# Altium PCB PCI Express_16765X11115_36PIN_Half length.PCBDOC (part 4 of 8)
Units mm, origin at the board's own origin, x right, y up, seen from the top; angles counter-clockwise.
Board outline 178 x 110.97 mm, 10 copper layers (Top Layer, Int1 (GND), Int2 (Sign), Int3 (Sign), Int4 (PWR), Int5 (GND), Int6 (Sign), Int7 (Sign), Int8 (GND), Bottom Layer), stack 1.429 mm thick; 528 components, 525 nets, 2272 pads, 1491 vias.
Unrouted connection lines stored in the file: 373.
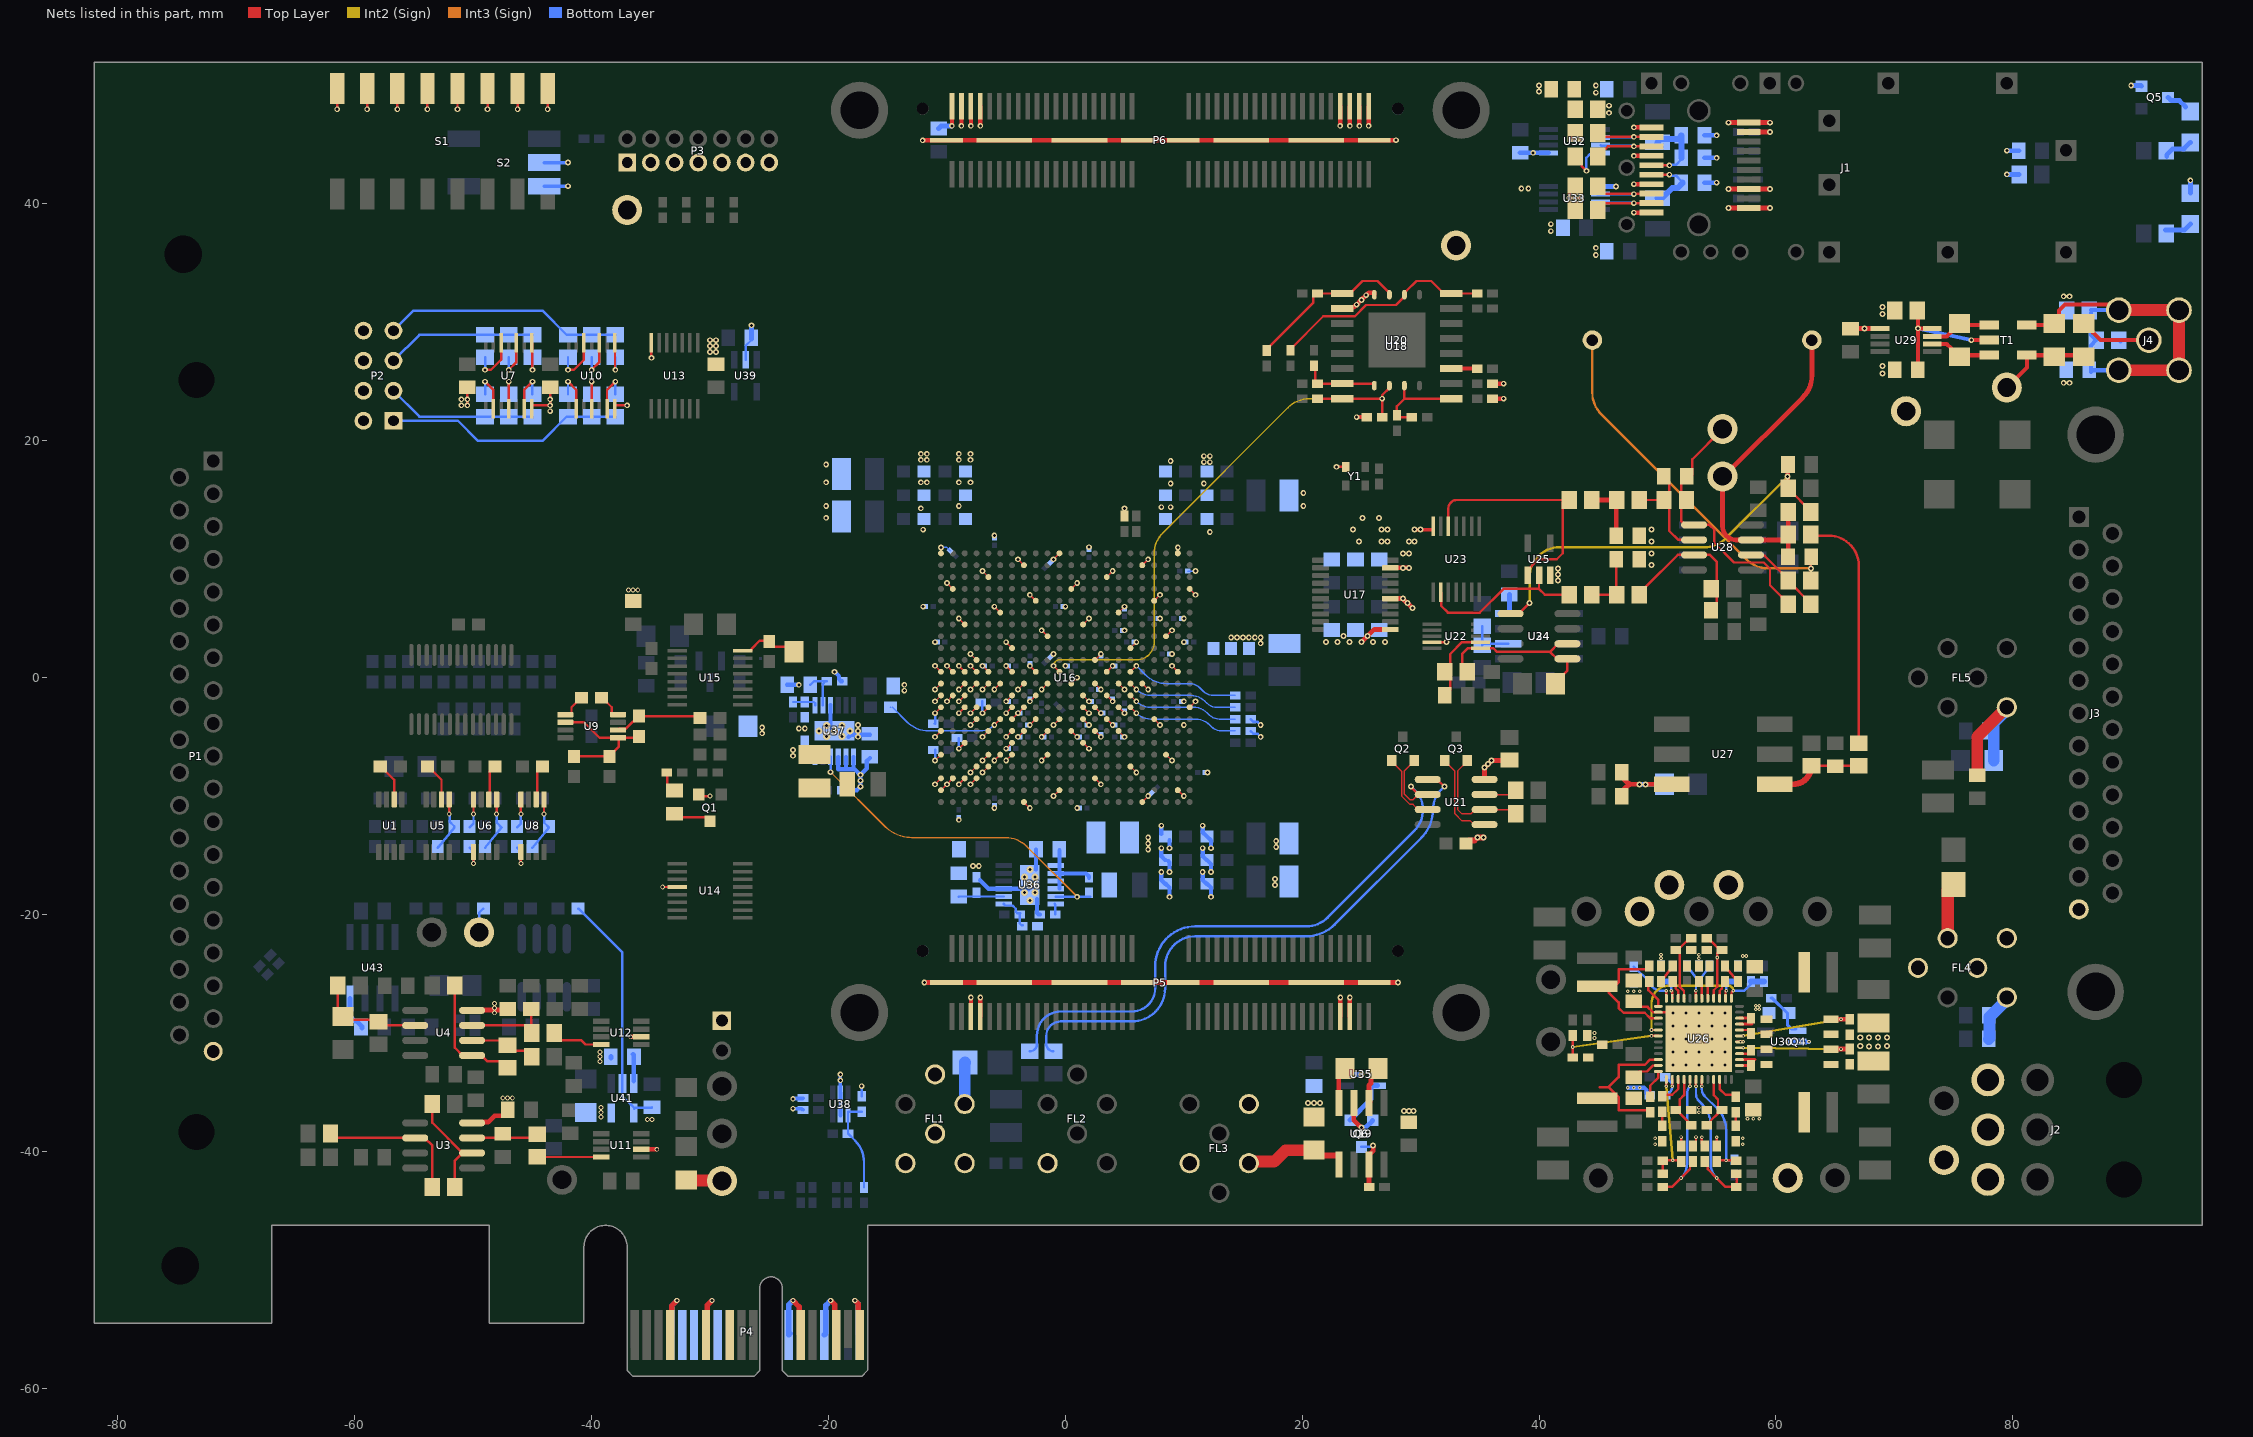
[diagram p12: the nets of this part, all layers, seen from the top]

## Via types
v1: diameter 0.483, hole 0.254, Top Layer to Bottom Layer, tented both sides, 740 vias
v2: diameter 0.508, hole 0.254, Top Layer to Bottom Layer, tented both sides, 302 vias
v3: diameter 0.406, hole 0.254, Top Layer to Bottom Layer, tented both sides, 267 vias
v4: diameter 0.305, hole 0.152, Top Layer to Bottom Layer, tented both sides, 95 vias
v5: diameter 0.5, hole 0.254, Top Layer to Bottom Layer, tented both sides, 50 vias
v6: diameter 0.45, hole 0.254, Top Layer to Bottom Layer, tented both sides, 23 vias
v7: diameter 0.6, hole 0.254, Top Layer to Bottom Layer, tented both sides, 14 vias

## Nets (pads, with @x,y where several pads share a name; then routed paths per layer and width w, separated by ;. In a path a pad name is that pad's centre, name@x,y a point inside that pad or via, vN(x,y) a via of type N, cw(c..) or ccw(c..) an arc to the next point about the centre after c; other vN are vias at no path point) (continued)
GND: C6.2 C12.2 C18.2 C23.2 C25.1 C26.1 C28.2 C29.2 C31.1 C32.1 C35.1 C37.1 C40.1 C41.2 C42.1 C43.2 C44.2 C45.1 C46.1 C50.1 C51.1 C52.2 C53.1 C56.1 C57.1 C58.2 C59.2 C67.2 C68.2 C69.1 C70.1 C73.2 C74.1 C75.2 C76.1 C77.2 C78.2 C79.2 C80.2 C83.1 C84.1 C85.1 C86.1 C87.1 C89.1 C91.1 C93.1 C94.1 C95.1 C96.1 C97.1 C98.1 C99.1 C100.1 C101.1 C102.1 C103.1 C104.1 C105.1 C106.1 C107.1 C108.1 C109.1 C110.1 C111.1 C112.1 C113.1 C114.1 C115.1 C116.1 C117.1 C118.1 C119.1 C120.1 C121.1 C122.1 C123.1 C124.1 C125.1 C126.1 C127.1 C128.1 C129.2 C130.1 C131.2 C132.1 C133.2 C134.1 C135.1 C136.2 C137.2 C138.1 C139.2 C140.1 C141.1 C142.1 C143.2 C144.2 C145.1 C147.1 C148.1 C149.1 C150.1 C151.2 C153.1 C154.1 C155.2 C156.2 C157.2 C158.1 C159.1 C160.2 C161.1 C162.1 C163.1 C164.1 C165.1 C166.1 C167.1 C168.1 C169.1 C170.1 C171.1 C172.1 C173.1 C174.1 C175.1 C176.1 C177.1 C178.1 C179.1 C180.1 C181.1 C182.1 C183.1 C184.1 C187.2 C188.2 C189.1 C192.1 DS2.1 FL1.3 FL1.4 FL1.5 FL1.6 FL2.3 FL3.3 FL4.3 FL4.4 FL4.5 FL4.6 FL5.3 FR4.1 J1.1 J1.3 J1.9 J1.10 J1.11 J1.14 J1.17 J1.20 J2.4 J2.5 J2.6 J3.13 P1.19 P2.2 P2.4 P2.6 P2.8 P3.1 P3.3 P3.5 P3.7 P3.9 P3.11 P3.13 P4.A4 P4.A12 P4.A15 P4.A18 P4.B4 P4.B7 P4.B13 P4.B16 P4.B18 P5.5 P5.7 P5.73 P5.75 P5.81 P5.82 P5.83 P5.84 P5.85 P5.86 P5.87 P5.88 P6.2 P6.4 P6.6 P6.8 P6.74 P6.76 P6.78 P6.80 P6.81 P6.82 P6.83 P6.84 P6.85 P6.86 P6.87 P6.88 Q1.2 Q4.1 Q4.3 Q5.2 Q6.2 R28.2 R36.2 R45.1 R52.2 R53.2 R54.1 R57.2 R69.2 R70.2 R71.2 R73.1 R74.2 R75.2 R76.2 R80.2 R81.2 R93.2 R94.2 R98.2 R106.2 R107.2 R114.1 R115.1 R119.2 R122.1 R124.1 R126.1 R131.2 R132.2 R137.1 R138.1 R143.1 R146.1 R149.1 R150.1 R151.1 S1.1 S1.2 S1.3 S1.4 S1.5 S1.6 S1.7 S1.8 S2.3 S2.5 TP4.1 TP8.1 TP13.1 TP14.1 TP18.1 TP20.1 TP23.1 TP24.1 U7.7 U10.7 U11.6 U12.6 U13.7 U14.12 U16.A2 U16.A3 U16.A5 U16.A7 U16.A9 U16.A10 U16.A11 U16.A12 U16.A22 U16.AA2 U16.AA12 U16.AA22 U16.AB9 U16.AB19 U16.B3 U16.B10 U16.B12 U16.B19 U16.C3 U16.C6 U16.C9 U16.C10 U16.C11 U16.C12 U16.C16 U16.D3 U16.D4 U16.D8 U16.D9 U16.D11 U16.D12 U16.D13 U16.E4 U16.E5 U16.E7 U16.E9 U16.E11 U16.E12 U16.E20 U16.F5 U16.F11 U16.F17 U16.G5 U16.G6 U16.G7 U16.G8 U16.G9 U16.G10 U16.G12 U16.G14 U16.H1 U16.H7 U16.H9 U16.H11 U16.H21 U16.J8 U16.J10 U16.J12 U16.J18 U16.K5 U16.K7 U16.K11 U16.K15 U16.L2 U16.L8 U16.L22 U16.M7 U16.M11 U16.M19 U16.N6 U16.N8 U16.N9 U16.N10 U16.N16 U16.P3 U16.P7 U16.P9 U16.P11 U16.P13 U16.R8 U16.R10 U16.R12 U16.R20 U16.T7 U16.T9 U16.T11 U16.T17 U16.U4 U16.U14 U16.V1 U16.V11 U16.V21 U16.W8 U16.W18 U16.Y5 U16.Y15 U17.11 U17.15 U17.19 U18.10 U19.3 U20.4 U21.4 U22.9 U23.7 U25.3 U26.2 U26.11 U26.30 U26.49 U29.5 U30.2 U32.5 U33.5 U35.2 U36.9 U36.13 U37.9 U37.13 U38.2 U38.5 U39.2 W1.1 Y1.2 | length 367.5
  Top Layer w0.127: v1(-11,-9) U16.A3@-10.5,-8.5 ; v1(-11,-7) U16.A5@-10.5,-6.5 ; v1(-11,-5) U16.A7@-10.5,-4.5 ; v1(-11,-3) U16.A9@-10.5,-2.5 ; v1(-11,-2) U16.A10@-10.5,-1.5 ; v1(-11,-1) U16.A11@-10.5,-0.5 ; v1(-11,1) U16.A12@-10.5,0.5 ; U16.A2@-10.5,-9.5 v1(-10,-9) U16.B3@-9.5,-8.5 ; U16.A22@-10.5,10.5 v1(-10.5,11) ; v1(-10,-2) U16.B10@-9.5,-1.5 ; v1(-10,1) U16.B12@-9.5,0.5 ; v1(-10,8) U16.B19@-9.5,7.5 ; v1(-9,-9) U16.C3@-8.5,-8.5 ; v1(-9,-6) U16.C6@-8.5,-5.5 ; v1(-9,-3) U16.C9@-8.5,-2.5 ; v1(-9,-2) U16.C10@-8.5,-1.5 ; v1(-9,-1) U16.C11@-8.5,-0.5 ; v1(-9,1) U16.C12@-8.5,0.5 ; v1(-9,5) U16.C16@-8.5,4.5 ; v1(-8,-9) U16.D3@-7.5,-8.5 ; v1(-8,-8) U16.D4@-7.5,-7.5 ; v1(-8,-4) U16.D8@-7.5,-3.5 ; v1(-8,-3) U16.D9@-7.5,-2.5 ; v1(-8,-1) U16.D11@-7.5,-0.5 ; v1(-8,1) U16.D12@-7.5,0.5 ; v1(-8,2) U16.D13@-7.5,1.5 ; v1(-7,-8) U16.E4@-6.5,-7.5 ; v1(-7,-7) U16.E5@-6.5,-6.5 ; v1(-7,-5) U16.E7@-6.5,-4.5 ; v1(-7,-3) U16.E9@-6.5,-2.5 ; v1(-7,-1) U16.E11@-6.5,-0.5 ; v1(-7,1) U16.E12@-6.5,0.5 ; v1(-7,9) U16.E20@-6.5,8.5 ; v1(-6,-7) U16.F5@-5.5,-6.5 ; v1(-6,-1) U16.F11@-5.5,-0.5 ; v1(-6,6) U16.F17@-5.5,5.5 ; v1(-5,-7) U16.G5@-4.5,-6.5 ; v1(-5,-6) U16.G6@-4.5,-5.5 ; v1(-5,-5) U16.G7@-4.5,-4.5 ; v1(-5,-3) U16.G9@-4.5,-2.5 ; v1(-5,-2) U16.G10@-4.5,-1.5 ; v1(-5,1) U16.G12@-4.5,0.5 ; v1(-5,3) U16.G14@-4.5,2.5 ; U16.G8@-4.5,-3.5 v1(-4,-3) U16.H9@-3.5,-2.5 ; v1(-4,-5) U16.H7@-3.5,-4.5 ; v1(-4,-1) U16.H11@-3.5,-0.5 ; v1(-4,10) U16.H21@-3.5,9.5 ; U16.H1@-3.5,-10.5 -3.514,-10.514 -3.029,-11 v1(-3,-11) ; v1(-3,-4) U16.J8@-2.5,-3.5 ; v1(-3,-2) U16.J10@-2.5,-1.5 ; v1(-3,1) U16.J12@-2.5,0.5 ; v1(-3,7) U16.J18@-2.5,6.5 ; v1(-2,-7) U16.K5@-1.5,-6.5 ; v1(-2,-5) U16.K7@-1.5,-4.5 ; v1(-2,-1) U16.K11@-1.5,-0.5 ; v1(-2,4) U16.K15@-1.5,3.5 ; v1(-1,-10) U16.L2@-0.5,-9.5 ; v1(-1,-4) U16.L8@-0.5,-3.5 ; v1(-1,10) U16.L22@-0.5,10.5 ; U16.M7@0.5,-4.5 v1(1,-5) ; U16.M19@0.5,7.5 v1(1,8) ; U16.N6@1.5,-5.5 v1(2,-6) ; U16.N8@1.5,-3.5 v1(2,-4) ; U16.N9@1.5,-2.5 v1(2,-3) ; U16.N10@1.5,-1.5 v1(2,-2) ; U16.N16@1.5,4.5 v1(2,5) ; U16.P3@2.5,-8.5 v1(3,-9) ; U16.P7@2.5,-4.5 v1(3,-5) ; U16.P9@2.5,-2.5 v1(3,-3) ; U16.P11@2.5,-0.5 v1(3,-1) ; U16.P13@2.5,1.5 v1(3,2) ; U16.R8@3.5,-3.5 v1(4,-4) ; U16.R10@3.5,-1.5 v1(4,-2) ; U16.R12@3.5,0.5 v1(4,1) ; U16.R20@3.5,8.5 v1(4,9) ; U16.T7@4.5,-4.5 v1(5,-5) ; U16.T9@4.5,-2.5 v1(5,-3) ; U16.T11@4.5,-0.5 v1(5,-1) ; U16.T17@4.5,5.5 v1(5,6) ; U16.U4@5.5,-7.5 v1(6,-8) ; U16.U14@5.5,2.5 v1(6,3) ; U16.V1@6.5,-10.5 v1(7,-10) ; U16.V11@6.5,-0.5 v1(7,-1) ; U16.V21@6.5,9.5 v1(7,10) ; U16.W8@7.5,-3.5 v1(8,-4) ; U16.W18@7.5,6.5 v1(8,7) ; U16.Y5@8.5,-6.5 v1(9,-7) ; U16.Y15@8.5,3.5 v1(9,4) ; v1(9,1) U16.AA12@9.5,0.5 ; U16.AA2@9.5,-9.5 v1(10,-10) ; U16.AA22@9.5,10.5 v1(9.5,11) ; U16.AB9@10.5,-2.5 v1(11,-2) ; U16.AB19@10.5,7.5 v1(11,7)
  Top Layer w0.203: v1(-61.49,48) S1.8@-61.49,49.75 ; v1(-58.95,48) S1.7@-58.95,49.75 ; v1(-56.41,48) S1.6@-56.41,49.75 ; v1(-53.87,48) S1.5@-53.87,49.75 ; v1(-51.33,48) S1.4@-51.33,49.75 ; v1(-50.5,23) C6.2@-50.5,24.5 ; v1(-48.79,48) S1.3@-48.79,49.75 ; v1(-46.25,48) S1.2@-46.25,49.75 ; U7.7@-45.05,22.725 -45.05,22.952 -45.002,23 v1(-43.5,23) C12.2@-43.5,24.525 C12.2@-43.5,24.6 ; v1(-43.71,48) S1.1@-43.71,49.75 ; U10.7@-38.05,22.725 -38.05,22.952 -38.002,23 v1(-37,23) ; U13.7@-34.95,28.275 -34.95,27.142 -34.908,27.1 v1@-34.9,27.1 ; v3(-34,-17.675) U14.12@-32.775,-17.675 ; Q1.2@-30.95,-9.875 -30.825,-10 v3(-30,-10) ; U16.M11@0.5,-0.5 v1(1,0) ; v1(22.9,17.8) Y1.2@23.7,17.8 ; U22.9@30.95,3 v2(32.2,3) ; C43.2@48,-33.725 48.473,-33.251 49.122,-33.251 49.623,-32.75 U26.11@50.075,-32.75 ; C44.2@48,-27.325 48.473,-27.798 49.173,-27.798 49.625,-28.25 51.25,-28.25 v5(53.5,-30.5) U26.49@53.25,-30.75 ; U26.49@51.3,-32.7 U26.49@53.25,-30.75 ; R71.2@52,-39.55 v4(52,-38.794) ; R73.1@53,-39.55 53.252,-39.298 v4(53.252,-38.794) ; U26.49@53.25,-31.6 U26.49@53.25,-30.75 ; v4(53.75,-38.8) 53.75,-39.3 R74.2@54,-39.55 ; R81.2@55,-39.55 v4(55,-38.8) ; U26.30@56.75,-30.75 U26.30@56.925,-30.75 v4(57.25,-30.75)
  Top Layer w0.3: v2(29.5,12.5) v2(30,12.5) U23.7@31,12.5
  Top Layer w0.35: v1(-9.58,46.6) P6.2@-9.58,48.245 ; v1(-8.78,46.6) P6.4@-8.78,48.245 ; P5.5@-7.98,-28.605 v1(-7.98,-27) ; v1(-7.98,46.6) P6.6@-7.98,48.245 ; P5.7@-7.18,-28.605 v1(-7.18,-27) ; v1(-7.18,46.6) P6.8@-7.18,48.245 ; v1(23.21,46.6) 23.21,48.22 cw(c23.244,48.22) P6.74@23.22,48.245 ; P5.73@23.22,-28.605 v1(23.22,-27) ; P5.75@24.02,-28.605 v1(24.02,-27) ; v1(24.02,46.6) P6.76@24.02,48.245 ; v1(24.6,22) R36.2@25.45,22 ; v1(24.82,46.6) P6.78@24.82,48.245 ; v1(25.62,46.6) P6.80@25.62,48.245
  Top Layer w0.4: v1(-11.902,-25.74) P5.81@-10.045,-25.74 P5.82@-5.155,-25.74 P5.83@1.195,-25.74 P5.84@6.085,-25.74 P5.85@9.955,-25.74 P5.86@14.845,-25.74 P5.87@21.195,-25.74 P5.88@26.085,-25.74 v1(28.085,-25.74) ; P6.81@-10.045,45.38 v1(-12.045,45.38) v1(-12.045,45.38) P6.88@26.086,45.382 ; U18.10@23.4,31.175 23.5,31.275 24.353,31.275 24.578,31.5 v1(24.6,31.5) v1(25,31.9) v1(25.4,32.3) 25.422,32.3 25.622,32.5 26.095,32.5 U20.4@26.095,32.34 ; v2(25,3) v2(25.5,3.5) 26.075,4.075 U17.11@27.45,4.075 ; P6.88@26.085,45.38 P6.88@26.086,45.382 ; v1@27.914,45.382 P6.88@26.086,45.382 ; U21.4@35.4,-8.595 35.4,-7.608 36,-7.008 v2(36,-7) 37.45,-7 R45.1@37.5,-6.95 ; v1(48,39.27) J1.20@49.5,39.27 ; v1(48,41.67) J1.17@49.5,41.67 ; v1(48,44.07) J1.14@49.5,44.07 ; v1(48,46.47) J1.11@49.5,46.47
  Top Layer w0.406: v3(-36.703,-30.325) U12.6@-35.8,-30.325 ; U11.6@-35.8,-39.825 v3(-34.5,-39.825) ; U19.3@24.357,-35.9 24.357,-37.357 v2(25,-38) ; U17.15@27.45,6.675 v2(28.497,6.675) 28.511,6.675 29.286,5.9 v2(29.3,5.9) ; U17.19@27.45,9.275 v2(28.5,9.275) v2(29,9.275) ; C31.1@36.07,24.825 v1(37.02,24.825) ; C32.1@36.07,23.555 v1(37.02,23.555) ; v1(56,39.67) J1.1@57.7,39.67 v1(59.5,39.67) ; v1(56,41.27) J1.3@57.7,41.27 v1(59.5,41.27) ; v1(56,46.87) J1.10@57.7,46.87 v1(59.5,46.87) ; J1.9@57.7,46.07 v1(59.5,46.07) ; C67.2@66,29.475 v2@67.56,29.475 ; v2(67.5,29.5) ccw(c67.56,29.56) v2@67.56,29.475 ; U29.5@68.805,29.475 v2@67.56,29.475
  Top Layer w0.455: P4.B4@-33.35,-55.5 -33.228,-55.377 -33.228,-53.015 v6(-32.806,-52.594) ; P4.B7@-30.35,-55.5 -30.228,-55.377 -30.228,-52.977 v6(-29.844,-52.594) ; v6(-23,-52.594) -22.473,-53.121 -22.473,-55.377 P4.B13@-22.35,-55.5 P4.B13@-22.227,-55.377 ; v6(-19.813,-52.594) -19.473,-52.934 -19.473,-55.377 P4.B16@-19.35,-55.5 ; v6(-17.781,-52.594) -17.473,-52.902 -17.473,-55.377 P4.B18@-17.35,-55.5
  Top Layer w0.5: C29.2@33.85,-14 34.1,-13.75 34.548,-13.75 34.798,-13.5 v2(34.8,-13.5) v2(35.3,-13.5)
  Top Layer w1: C73.2@77,-8.225 77,-5 FL5.3@79.5,-2.5
  Bottom Layer w0.127: C174.1@-11.1,-3.9 C174.1@-11,-3.8 ; v1(-10.5,11) -10,11 C172.1@-9.7,10.7 ; C153.1@-3.096,-2.003 v1@-3,-2.1 ; C153.1@-3.028,-1.972 v1(-3,-2) ; 8.8,-14.025 C118.1@8.8,-13.599 ; C115.1@10.33,9 v1(11,9)
  Bottom Layer w0.203: U39.2@-27,26.85 -27,27.783 -26.998,27.784 -26.998,28.027 C192.1@-26.525,28.5 ; R146.1@-17.2,-35.35 v6(-17.2,-34.5) ; v1(-11,-7) C173.1@-11,-6.1 ; C174.1@-11,-3.9 v1(-11,-3) ; v1(-9,-6) C166.1@-9,-5.1 ; v1(-7,-3) C161.1@-7,-2 ; R131.2@15.65,-4.5 15.883,-4.733 16.241,-4.733 v1@16.508,-5 ; R132.2@15.65,-3.5 15.887,-3.737 16.237,-3.737 v1(16.5,-4)
  Bottom Layer w0.3: S2.3@-44,41.5 v1(-42,41.5) ; S2.5@-44,43.5 v1(-42,43.5) ; v6(-23,-36.4) -22.25,-36.4 C187.2@-22.15,-36.5 ; v6(-23,-35.563) -22.971,-35.534 -22.184,-35.534 C188.2@-22.15,-35.5 ; U38.2@-19,-35.05 v6(-19,-34) v6(-19,-33.5)
  Bottom Layer w0.35: C189.1@-23.5,-0.6 C189.1@-23.475,-0.6 v1(-22.5,-0.6) ; U37.9@-19.825,-2.316 -19.825,-4.175 v7(-19.5,-4.5) ; v1(-19.5,0.5) -19.125,0.125 -19.125,-0.125 -18.95,-0.3 R149.1@-18.85,-0.3 ; U38.5@-19,-36.95 U38.2@-19,-35.05 ; U37.13@-18.3,-5 cw(c-17.878,-5.422) -17.878,-4.825 C184.1@-16.5,-4.825 ; R143.1@-7.2,-17.1 -7.102,-17.198 -6.475,-17.825 U36.9@-5.184,-17.825 -3.175,-17.825 cw(c-3.175,-17.9) U36.13@-3.1,-17.9 ; U36.13@-2.5,-16.2 -2.475,-16.175 C148.1@-2.475,-14.5 ; U36.13@-2.4,-18.7 -2.4,-19.75 ccw(c-2.15,-19.75) R137.1@-2.15,-20 ; v1(8.1,-16.4) 8.1,-17.075 8.425,-17.4 C116.1@8.45,-17.4 8.475,-17.4 8.8,-17.725 v1(8.8,-18.5) ; v1(8.1,-14.4) 8.1,-15.075 8.425,-15.4 C117.1@8.45,-15.4 ; C118.1@8.1,-13.2 v1(8.1,-12.5) ; C117.1@8.7,-15.5 8.8,-15.6 v1(8.8,-16.4) ; v1(8.8,-14.4) C118.1@8.8,-13.725 ; v1(11.6,-16.4) 11.6,-17.075 11.925,-17.4 C106.1@11.95,-17.4 11.975,-17.4 12.3,-17.725 v1(12.3,-18.5) ; v1(11.6,-14.4) 11.6,-15.075 11.925,-15.4 C107.1@11.95,-15.4 11.975,-15.4 12.3,-15.725 v1(12.3,-16.4) ; v1(11.6,-12.5) 11.6,-13.05 C108.1@11.95,-13.4 11.975,-13.4 12.3,-13.725 v1(12.3,-14.4) ; v4(47.5,-34.625) v4(48,-34.625) v4(48.5,-34.625) 48.87,-34.625 49.075,-34.83 49.075,-35.075 49.25,-35.25 R122.1@49.35,-35.25 ; v4(60.9,-30.75) v4(62.8,-30.75)
  Bottom Layer w0.4: v1(16.5,-5) v1@16.508,-5 ; U35.2@23.65,-33.5 v2(25,-33.5)
  Bottom Layer w0.406: C192.1@-26.5,28.6 v1(-26.5,29.756) ; C176.1@-10.7,46.375 -10.49,46.585 -9.615,46.585 v1@-9.6,46.6 ; v2(25,-38) 25.02,-37.98 25.37,-37.98 25.95,-37.4 Q6.2@25.95,-37.375 ; C91.1@38.4,44.325 v1(39.5,44.325) U32.5@40.805,44.325 ; U33.5@45.195,41.475 v1(46.5,41.475) ; C83.1@53.975,41.8 v1(55,41.8) ; C84.1@53.975,43.9 v1(55,43.9) ; C85.1@53.975,45.8 v1(55,45.8) ; v1(79.5,42.5) R107.2@80.55,42.5 ; v1(79.5,44.5) C75.2@80.525,44.5 ; v1@90.1,50 90.825,50 Q5.2@90.875,49.95 ; DS2.1@95,40.9 v1(95,42)
  Bottom Layer w0.455: P4.A4@-33.35,-55.5 -33.228,-55.377 -33.228,-53.015 v6(-32.806,-52.594) ; P4.A12@-23.227,-55.377 P4.A12@-23.35,-55.5 -23.35,-52.944 v6(-23,-52.594) ; P4.A15@-20.35,-55.5 -20.227,-55.377 -20.227,-53.009 v6(-19.813,-52.594) ; v6(-17.781,-52.594) -17.473,-52.902 -17.473,-55.377 P4.A18@-17.35,-55.5
  Bottom Layer w1: C77.2@77.975,-30.5 78.05,-30.425 78.05,-28.639 79.5,-27.189 FL4.3@79.5,-27 ; C76.1@78.4,-7 78.4,-3.789 79.5,-2.689 FL5.3@79.5,-2.5
  other v1: 17.7,-17.5 17.7,-17 -7.8,-15.9 -7.3,-15.9 7,-14.5 17.8,-14.3 7,-14 17.8,-13.8 7,-13.5 -9,-12 -6,-11 1,-11 12,-8 -23,-6.6 -23,-6.1 -17.5,-5 -25.6,-4.7 -17.5,-4.5 -22.5,-4.3 -22,-4.3 -25.6,-4.2 -17.5,-4 10,-4 10,-2 -13.6,-1.1 -13.6,-0.6 0,1 -1,2 9,2 16.5,2.9 -11,3 10,3 14,3.4 14.5,3.4 15,3.4 15.5,3.4 16,3.4 16.5,3.4 5,4 8,5 10,5 -12,6 0,6 2,11.019 -6,12 12.2,12.3 -12,12.5 -20.2,13.5 -12.2,14.3 5,14.3 8.1,14.4 8.9,14.4 -20.2,14.5 -9,14.5 20.1,14.5 20.1,15.6 8.9,16.4 11.7,16.4 -20.2,16.5 -12.2,16.5 -11.7,16.5 -9,16.5 -8,16.5 -20.2,18 11.7,18.2 12.2,18.2 8.9,18.3 -12.2,18.4 -11.7,18.4 -9,18.4 -8,18.4 11.7,18.7 12.2,18.7 -12.2,18.9 -11.7,18.9 -9,18.9 -8,18.9 -43.5,22.5 -51,23 -51,23.5 -50.5,23.5 -43.5,23.5 84.3,24.9 84.8,24.9 -34.95,27.013 -30,27.5 -29.5,27.5 -30,28 -29.5,28 -30,28.5 -29.5,28.5 84.3,32.2 84.8,32.2 44.8,35.7 44.8,36.3 41,37.7 41,38.3 42.546,40.497 43.046,40.497 43.546,40.497 38.5,41.3 39.1,41.3 27.915,45.383 45.9,47.7 45.9,48.3 44.8,49.4 40,49.5 40,50 44.8,50 90,50
  other v2: 28.6,-36.6 29,-36.6 29.4,-36.6 20.5,-35.9 21,-35.9 21.5,-35.9 67.875,-31.125 68.625,-31.125 67.125,-31.108 69.375,-31.101 67.125,-30.375 67.875,-30.375 68.625,-30.375 69.375,-30.375 35.4,-7.6 35.7,-7.3 22,3 23,3 24,3 26,3 27,3 23.5,3.5 28.9,6.3 41.6,8.2 41.6,8.7 41.6,9.2 49.5,9.5 28.5,10.5 29,10.5 49.5,10.5 24.8,11.5 26.7,11.5 27.2,11.5 29,11.5 29.5,11.5 49.5,11.5 24.3,12.5 26.7,12.5 27.2,12.5 49.5,12.5 25.1,13.5 26.5,13.5 69,25.7 69,26.3 69,30.7 69,31.3
  other v3: -36.9,7.4 -36.5,7.4 -36.1,7.4
  other v4: 49.8,-39.4 57.2,-39.4 49.8,-38.9 57.2,-38.9 57.6,-37.25 58.1,-37.25 58.6,-37.25 53.5,-36.7 53.5,-36.3 57,-30.75 44.687,-30.431 44.687,-30 58.3,-28 58.6,-28 58.3,-27.7 58.6,-27.7 47.5,-26.477 48,-26.477 48.5,-26.477 50.3,-23.7 53.5,-23.7 57.2,-23.5 57.5,-23.5 50.3,-23.4 53.5,-23.4
  other v5: 51.3,-32.7 52.4,-32.7 53.5,-32.7 54.6,-32.7 55.7,-32.7 51.3,-31.6 52.4,-31.6 53.5,-31.6 54.6,-31.6 55.7,-31.6 51.3,-30.5 52.4,-30.5 54.6,-30.5 55.7,-30.5 51.3,-29.4 52.4,-29.4 53.5,-29.4 54.6,-29.4 55.7,-29.4 51.3,-28.3 52.4,-28.3 53.5,-28.3 54.6,-28.3 55.7,-28.3
  other v7: -3,-18.8 -3.45,-18.15 -2.55,-18.15 -3,-17.5 -3.45,-16.85 -2.55,-16.85 -3,-16.2 -20.15,-4.95 -18.85,-4.95 -20.8,-4.5 -18.2,-4.5 -20.15,-4.05 -18.85,-4.05
INIT: R134.1 U16.U12 | length 9.9
  Top Layer w0.127: U16.U12@5.5,0.5 v1(6,1)
  Bottom Layer w0.127: v1(6,1) 6.756,0.244 ccw(c8.552,2.04) 8.552,-0.5 10.5,-0.5 cw(c10.5,-1.707) 11.353,-0.853 11.646,-1.146 ccw(c12.5,-0.293) 12.5,-1.5 R134.1@14.35,-1.5
JTAG1: P4.B9
JTAG2: P4.A5
JTAG3: P4.A6
JTAG4: P4.A7
JTAG5: P4.A8
M0: R133.1 U16.U11 | length 9.5
  Top Layer w0.127: U16.U11@5.5,-0.5 v1(6,-1)
  Bottom Layer w0.127: v1(6,-1) ccw(c7.207,0.207) 7.207,-1.5 10.593,-1.5 cw(c10.593,-3.207) 11.8,-2 11.946,-2.146 ccw(c12.8,-1.293) 12.8,-2.5 R133.1@14.35,-2.5
M1: R132.1 U16.U10 | length 9.5
  Top Layer w0.127: U16.U10@5.5,-1.5 v1(6,-2)
  Bottom Layer w0.127: v1(6,-2) ccw(c7.207,-0.793) 7.207,-2.5 10.793,-2.5 cw(c10.793,-4.207) 12,-3 12.146,-3.146 ccw(c13,-2.293) 13,-3.5 R132.1@14.35,-3.5
M2: R131.1 U16.U9 | length 9.5
  Top Layer w0.127: U16.U9@5.5,-2.5 v1(6,-3)
  Bottom Layer w0.127: v1(6,-3) ccw(c7.207,-1.793) 7.207,-3.5 10.993,-3.5 cw(c10.993,-5.207) 12.2,-4 12.346,-4.146 ccw(c13.2,-3.293) 13.2,-4.5 R131.1@14.35,-4.5
MON: C65.2 R90.2 R91.1 U24.5 | length 35.6
  Top Layer w0.203: U24.5@37.6,5.405 38.305,5.405 v2(39.2,6.3) ; R91.1@60.685,16.365 61,16.05 R91.1@61.05,16 R90.2@62.95,14 ; C65.2@60.685,17.61 61,17.925 61.05,17.975 ccw(c61.025,17.975) C65.2@61.025,18
  Top Layer w0.406: U24.5@37.6,5.4 U24.5@37.6,5.405 ; C65.2@61.025,18 ccw(c61.025,17.975) 61,17.975 61,17.925 v2(61,17) 61,16.05 ccw(c61.05,16.05) R91.1@61.05,16
  Int2 (Sign) w0.203: v2(39.2,6.3) 39.2,8.475 cw(c41.74,8.475) 41.74,11.015 53.963,11.015 ccw(c53.963,13.555) 55.759,11.759 v2(61,17)
N5V: C9.1 C10.1 C197.1 C200.2 R180.1 TP2.1 U3.4 U4.4 U41.5 | length 9.1
  Top Layer w0.406: U3.4@-50.1,-37.595 -50.063,-37.558 -49.126,-37.558 -49.099,-37.532 -48.732,-37.532 -48.197,-36.997 -47.597,-36.997 -47.1,-36.5 C9.1@-47.1,-36.2 ; U4.4@-50.1,-28.095 -50.063,-28.058 -47.183,-28.058 C10.1@-47.1,-27.975
  Bottom Layer w0.203: TP2.1@-49.5,-21.5 -49.5,-19.85 R180.1@-49.15,-19.5
  Bottom Layer w0.406: C197.1@-38.375,-32.125 C197.1@-38.375,-32
  other v3: -39.2,-37.1 -39.2,-36.7 -39.2,-36.3 -47.5,-35.5 -47.1,-35.5 -46.7,-35.5 -39.3,-32.4 -39.3,-32 -39.3,-31.6 -48.2,-28.3 -48.2,-27.9 -48.2,-27.5
N12V: C20.2 C195.2 FL3.2 R159.1 TP5.1 U41.2 U41.4 | length 23.7
  Top Layer w1: C20.2@-32.2,-42.5 -32.15,-42.45 -29.05,-42.45 TP5.1@-29,-42.5
  Bottom Layer w0.203: R159.1@-41.15,-19.5 -41.1,-19.5 -37.4,-23.2 U41.2@-37.4,-34.25 -37.4,-35.355 -36.703,-36.052 -36.673,-36.052 -36.4,-36.325 U41.4@-36.4,-36.4 ; U41.4@-36.4,-36.3 -34.925,-36.3 C195.2@-34.9,-36.275
  other v3: -35.3,-37.3 -34.9,-37.3
NetC1_2: C1.2 R3.2 R4.1 U4.6 | length 8
  Top Layer w0.203: R3.2@-61.45,-26 -61.45,-27.95 C1.2@-61.2,-28.2 ; C1.2@-60.5,-28.9 -58.15,-28.9 R4.1@-58,-29.05 ; R4.1@-58,-29.4 -57.965,-29.365 U4.6@-54.9,-29.365
NetC8_1: C8.1 R15.2 U3.3 | length 5.5
  Top Layer w0.203: U3.3@-50.1,-38.865 -45.165,-38.865 R15.2@-44.8,-38.5 ; R15.2@-44.8,-38.55 R15.2@-44.775,-38.525
NetC11_2: C11.2 R14.2 U4.3 | length 7.5
  Top Layer w0.203: U4.3@-50.1,-29.365 -45.535,-29.365 R14.2@-45.1,-29.8 ; R14.2@-45.1,-30.2 R14.2@-45.1,-29.8 ; C11.2@-45.1,-27.975 R14.2@-45.1,-29.8 ; C11.2@-45.05,-27.85 C11.2@-45,-27.8
NetC24_2: C24.2 FR2.1 U15.16 | length 5.1
  Top Layer w0.203: U15.16@-27.225,2.275 -26.55,2.275 -26.502,2.323 -26.502,2.428 -25.805,3.125 C24.2@-25,3.125 ; C24.2@-25,3.053 -25,3.003 -24.602,2.604 -23.004,2.604 FR2.1@-22.8,2.4
NetC25_2: C25.2 C184.2 L1.1 R148.2 U37.1 U37.2 U37.3 | length 9.6
  Bottom Layer w0.35: U37.3@-19.175,-6.684 -19.175,-7.727 -18.492,-7.727 ; R148.2@-18.85,-9.5 -17.593,-9.5 -17.3,-9.207 v1(-17.3,-9.2) v1(-17.3,-8.7) v1(-17.3,-8.2) ; U37.2@-18.525,-6.684 -18.525,-7.694 -18.492,-7.727 ; -17.875,-7.727 U37.1@-17.875,-6.684 ; C184.2@-16.5,-6.775 -16.77,-7.045 -16.77,-7.67 v1(-17.3,-8.2) ; -18.492,-7.727 -17.809,-7.727 -17.336,-8.2 v1(-17.3,-8.2)
NetC26_2: C26.2 FL3.1 U19.5 | length 8.7
  Top Layer w0.5: C26.2@21.2,-39.9 21.65,-40.35 23.045,-40.35 23.095,-40.4 U19.5@23.095,-41.1
  Top Layer w1: FL3.1@15.5,-41 15.634,-40.866 17.634,-40.866 18.6,-39.9 C26.2@20.9,-39.9
NetC27_1: C27.1 U19.4 | length 3.2
  Top Layer w0.406: U19.4@23.095,-35.9 23.095,-33.405 C27.1@23.6,-32.9
NetC27_2: C27.2 U19.2 | length 3.4
  Top Layer w0.406: U19.2@25.732,-35.803 U19.2@25.635,-35.9 25.635,-34.422 25.8,-34.257 25.8,-33.935 25.803,-33.932 25.803,-33.597 C27.2@26.4,-33
NetC30_2: C30.2 R41.1 U22.2 | length 7.8
  Top Layer w0.203: C30.2@32.025,-1.5 32.498,-1.027 R41.1@32.498,0.948 ; R41.1@32.05,0.5 R41.1@32.498,0.948 ; U22.2@35.05,3 33.5,3 32.5,2 32.5,1.475 ; R41.1@32.498,0.948 32.5,0.95 32.5,1.475 ; R41.1@32.498,0.948 32.498,1.473 32.5,1.475
NetC34_1: C34.1 R41.2 U22.1 U24.1 U24.2 | length 15.4
  Top Layer w0.203: R41.2@33.95,0.5 33.5,0.95 33.5,2 34,2.5 U22.1@35.05,2.5 36.14,2.5 36.458,2.183 40.918,2.183 ; C34.1@41.4,-0.5 41.4,-0.4 42.098,0.299 42.4,0.6 U24.1@42.4,1.595 41.505,1.595 40.918,2.183 ; U24.2@42.4,2.865 41.6,2.865 40.918,2.183
NetC35_2: C35.2 R55.1 R56.1 R57.1 U32.4 | length 3
  Top Layer w0.203: 43.598,43.202 v1(44,42.8)
  Bottom Layer w0.203: v1(44,42.8) 44,43.9 44.317,44.217 45.097,44.217 U32.4@45.205,44.325
NetC36_1: C36.1 C64.2 R89.2 | length 31.4
  Top Layer w0.203: R89.2@62.95,8 R89.2@62.95,8.2 v2(62.95,9.237) 62.95,9.975 C64.2@62.975,10
  Int3 (Sign) w0.203: C36.1@44.5,28.5 44.5,24.054 ccw(c47.04,24.054) 45.244,22.258 57.52,9.981 ccw(c59.316,11.777) 59.316,9.237 v2(62.95,9.237)
NetC36_2: C36.2 C64.1 R87.2 R90.1 TP16.1 U28.7 | length 29.1
  Top Layer w0.406: C64.1@61.025,10 61.05,10.025 R90.1@61.05,14 ; R87.2@61.05,12 60.685,11.635 U28.7@57.9,11.635 56.644,11.635 cw(c56.644,12.779) 55.5,12.779 55.5,16.9 cw(c55.6,16.9) 55.6,17 62.298,23.698 ccw(c60.502,25.494) 63.042,25.494 C36.2@63.042,28.5
NetC38_2: C38.2 C39.2 FR3.1 U27.6 | length 8.1
  Top Layer w0.381: C38.2@46.975,-10 cw(c47.975,-10) 47.975,-9 ; C39.2@46.975,-8 ccw(c47.975,-8) 47.975,-9 ; v2(48.5,-9) 47.975,-9 ; v2(49,-9) U27.6@51.2,-9
  Bottom Layer w0.381: v2(48.5,-9) v2(49,-9) FR3.1@50.6,-9 FR3.1@50.7,-9
NetC41_1: C41.1 R51.2 R60.1 | length 5.1
  Top Layer w0.406: R51.2@44.45,15 R60.1@46.55,15 ccw(c46.61,14.94) 46.525,14.94 C41.1@46.525,12
NetC42_2: C42.2 R50.2 R59.1 | length 5.3
  Top Layer w0.203: R50.2@44.45,7 R59.1@46.525,7 ; R59.1@46.5,6.9 46.525,6.925 R59.1@46.525,7 ; C42.2@46.525,10 R59.1@46.525,7 ; R59.1@46.6,7 R59.1@46.55,7 R59.1@46.525,7
NetC47_1: C47.1 L3.1 U26.3 | length 10.8
  Top Layer w0.203: C47.1@49.225,-24.625 46.723,-24.625 46.723,-25.726 ; C47.1@49.3,-24.575 C47.1@49.45,-24.425 ; U26.3@50.075,-28.75 49.372,-28.75 48.922,-28.3 47.134,-28.3 46.723,-27.889 46.723,-27.423 45.875,-26.575 L3.1@46.444,-26.006 ; L3.1@46.444,-26.006 46.723,-25.726 ; L3.1@46.444,-26.006 46.723,-25.726
NetC47_2: C47.2 U26.1 | length 2.4
  Top Layer w0.203: C47.2@49.225,-25.7 49.225,-26.38 50.075,-27.23 U26.1@50.075,-27.75
NetC48_1: C48.1 L2.1 U26.10 | length 11.5
  Top Layer w0.203: 45.125,-34.575 45.875,-34.575 ; C48.1@49.375,-36.525 46.723,-36.525 46.723,-35.423 46.467,-35.166 45.875,-34.575 ; U26.10@50.075,-32.25 49.375,-32.25 48.925,-32.7 46.723,-32.7 46.723,-33.726 45.875,-34.575
NetC48_2: C48.2 U26.12 | length 2.3
  Top Layer w0.203: C48.2@49.375,-35.225 49.375,-34.461 50.075,-33.761 U26.12@50.075,-33.25
NetC49_1: C49.1 R64.2 R88.1 TP17.1 U28.1 | length 22.4
  Top Layer w0.203: C49.1@52.475,17 52.002,16.527 52.002,16.002 52,16 52,15 52.002,14.998 52.002,13.222 52.319,12.905 54.395,12.905 54.8,12.5 54.8,11.4 56.471,9.729 58.97,9.729 59.5,9.199 59.5,7.8 60.451,6.849 60.502,6.849 61.05,6.3 R88.1@61.05,6.2 ; C49.1@52.9,17.1 52.948,17.148 52.948,18.449 TP17.1@55.5,21
NetC49_2: C49.2 R60.2 R64.1 U28.2 | length 10.1
  Top Layer w0.203: R60.2@48.45,15 R64.1@50.55,15 ; C49.2@50.525,17 50.998,16.527 R64.1@50.998,15.102 ; 51,15.9 51,12.4 51.765,11.635 U28.2@53.1,11.635
NetC50_2: C50.2 R66.1 | length 1.6
  Top Layer w0.203: C50.2@50.3,-25.65 R66.1@51.3,-24.35
NetC51_2: C51.2 R65.1 | length 1.1
  Top Layer w0.203: R65.1@50.398,-36.525 50.398,-37.598 C51.2@50.4,-37.6
NetC53_2: C53.2 U26.42 | length 1.4
  Top Layer w0.203: C53.2@53.5,-25.775 53.748,-26.023 53.748,-27.073 U26.42@53.75,-27.075
NetC55_2: C55.2 R59.2 R79.1 U28.3 | length 13
  Top Layer w0.203: R59.2@48.45,7 48.45,7.1 48.999,7.649 51.715,10.365 U28.3@53.1,10.365 54.435,10.365 55,9.8 R79.1@55,7.95 ; R79.1@54.55,7.5 R79.1@55,7.95 ; C55.2@55,5.7 R79.1@55,7.95
NetC56_2: C56.2 R86.1 | length 1.1
  Top Layer w0.203: C56.2@56.6,-37.65 R86.1@56.6,-36.55
NetC57_2: C57.2 R82.1 | length 1.7
  Top Layer w0.203: R82.1@55.7,-24.35 C57.2@56.75,-25.65
NetC60_1: C60.1 U26.28 | length 1.5
  Top Layer w0.203: U26.28@56.928,-31.753 56.925,-31.75 C60.1@58.002,-31.75 ; C60.1@57.753,-31.101 58.002,-31.35 C60.1@58.002,-31.45
NetC60_2: C60.2 L4.1 Q4.7 Q4.8 U26.26 U26.27 | length 2.3
  Top Layer w0.254: U26.26@56.925,-32.75 C60.2@57.902,-32.75 ; U26.27@56.925,-32.25 58.25,-32.25
NetC61_1: C61.1 U26.32 | length 1.7
  Top Layer w0.203: U26.32@56.927,-29.748 U26.32@56.925,-29.75 C61.1@58.15,-29.75 ; C61.1@57.653,-30.398 57.902,-30.15 C61.1@57.902,-30.05
NetC61_2: C61.2 L5.1 Q4.5 Q4.6 U26.33 U26.34 | length 2
  Top Layer w0.254: U26.33@56.925,-29.25 57.977,-29.25 ; U26.34@56.925,-28.75 C61.2@57.902,-28.75
NetC66_1: C66.1 R92.1 R95.1 U27.1 | length 8.2
  Top Layer w0.203: R92.1@63,-7.45 R95.1@67,-7.45 67.15,-7.45 cw(c67.15,-7.5) R95.1@67.2,-7.5
  Top Layer w0.5: U27.1@59.9,-9 61.45,-9 ccw(c61.45,-7.45) R92.1@63,-7.45
NetC70_2: C70.2 R98.1 T1.2 U29.4 | length 12.4
  Top Layer w0.35: R98.1@71.95,31 72,30.95 v1(72,29.5) ; C70.2@71.975,26 72,26.025 v1(72,29.5) ; U29.4@73.205,29.475 73.18,29.5 v1(72,29.5) ; v1(76.5,28.5) T1.2@78,28.5
  Bottom Layer w0.35: v1(72,29.5) v1(76.5,28.5)
NetC74_2: C74.2 J4.2 R101.1 R105.1 R106.1 T1.4 | length 34.5
  Top Layer w0.35: T1.4@81.175,29.77 83.73,29.77 R101.1@83.8,29.7 ; R101.1@83.5,29.9 83.92,30.32 83.92,31.02 84.4,31.5 88.01,31.5 88.124,31.386 J4.2@88.686,31.386
  Top Layer w1: J4.2@88.96,25.96 93.962,25.96 ccw(c93.962,26.438) J4.2@94.3,26.1 ; J4.2@88.96,31.04 93.903,31.04 cw(c93.903,30.903) J4.2@94,31 ; J4.2@94.04,31.04 94.04,26.145 ccw(c94.245,26.145) J4.2@94.1,26
  Bottom Layer w0.35: C74.2@86.6,25.8 C74.2@86.6,25.96 ; R106.1@86.6,30.8 86.6,28.95 R105.1@87.05,28.5 86.6,28.05 C74.2@86.6,25.96 ; R106.1@86.6,31.04 J4.2@88.96,31.04 ; J4.2@88.96,25.96 C74.2@86.6,25.96
NetC80_1: C80.1 R108.1 U30.1 | length 3.7
  Bottom Layer w0.254: R108.1@59.6,-27.062 59.7,-27.062 61.002,-28.364 61.002,-29.352 61.3,-29.65 U30.1@61.69,-29.65
NetC83_2: C83.2 J1.16 L6.1 | length 5.8
  Top Layer w0.203: J1.16@49.3,42.4 49.37,42.47 J1.16@49.5,42.47 v1(51,42.47)
  Bottom Layer w0.203: v1@51,42.4 51.017,42.417 51.129,42.417 51.147,42.398 51.552,42.398 52.025,41.925 C83.2@52.025,41.8
  Bottom Layer w0.5: L6.1@50,40.5 50.4,40.5 51.25,41.35 51.7,41.35 52.1,41.75 C83.2@52.1,41.8
NetC84_2: C84.2 C85.2 J1.15 L7.1 | length 7.6
  Top Layer w0.203: J1.15@49.3,43.2 49.37,43.27 J1.15@49.5,43.27 v1(51,43.27)
  Bottom Layer w0.203: L7.1@50,45.2 L7.1@50.419,44.781 ; v1@51,43.3 51.002,43.302 51.552,43.302 52.025,43.775 C84.2@52.025,43.9
  Bottom Layer w0.5: L7.1@50,45.2 50.3,45.5 51.8,45.5 C85.2@51.9,45.6 ; C85.2@52,45.8 52.025,45.775 52.025,45.5 C84.2@52.025,43.9
NetC92_2: C92.2 U34.4 | length 1.7
  Bottom Layer w0.406: U34.4@37.4,5.405 37.403,5.405 37.5,5.502 C92.2@37.5,7.025
NetC128_2: C128.2 C148.2 L8.1 R135.2 U36.1 U36.2 U36.3 U36.4 | length 6.3
  Bottom Layer w0.35: U36.2@-0.816,-16.525 U36.2@-0.5,-16.525 ; U36.4@-0.5,-17.8 -0.5,-17.175 U36.2@-0.5,-16.525 ; C148.2@-0.5,-14.575 -0.5,-15.875 U36.2@-0.5,-16.525 ; R135.2@2,-16.9 R135.2@2,-16.85 2,-16.773 1.752,-16.525 U36.2@-0.5,-16.525
NetC170_2: C170.2 R143.2 U36.8 | length 3.8
  Bottom Layer w0.203: C170.2@-9,-18.5 -8.975,-18.475 U36.8@-5.184,-18.475
NetC189_2: C189.2 R149.2 U37.8 | length 3.6
  Bottom Layer w0.203: C189.2@-21.525,-0.6 -21.225,-0.3 R149.2@-20.227,-0.3 ; U37.8@-20.475,-2.316 -20.475,-0.548 R149.2@-20.227,-0.3 ; R149.2@-20.15,-0.3 R149.2@-20.227,-0.3
NetC197_2: C197.2 U41.3 | length 2.3
  Bottom Layer w0.406: C197.2@-36.5,-31.8 -36.437,-31.863 -36.437,-34.037 U41.3@-36.45,-34.05
NetC210_1: C210.1 U43.4 | length 3
  Bottom Layer w0.406: U43.4@-60.405,-27.1 -60.405,-28.595 -59.997,-29.003 -59.847,-29.003 -59.4,-29.45 C210.1@-59.4,-29.6
NetD1_1: D1.1 FL4.2 | length 4.7
  Top Layer w1.07: FL4.2@74.5,-22 74.51,-21.99 74.51,-17.965 D1.1@75,-17.475
NetD2_1: D2.1 FL1.2 | length 3.5
  Bottom Layer w1: FL1.2@-8.5,-36 -8.5,-32.56 cw(c-8.415,-32.56) D2.1@-8.475,-32.5
NetDS1_1: DS1.1 Q1.3 | length 3.5
  Top Layer w0.203: DS1.1@-33.4,-11.8 -30.325,-11.8 Q1.3@-30,-12.125
NetDS1_2: DS1.2 R21.2 | length 1.9
  Top Layer w0.203: R21.2@-33.6,-7.9 -33.6,-8.925 -33.598,-8.927 -33.598,-9.052 -33.125,-9.525 DS1.2@-33,-9.525
NetDS2_2: DS2.2 R103.1 | length 2.3
  Bottom Layer w0.406: R103.1@92.9,37.8 94.5,37.8 DS2.2@95,38.3
NetDS3_1: DS3.1 Q5.3 | length 1.8
  Bottom Layer w0.406: Q5.3@93.125,49 93.397,48.728 94.072,48.728 DS3.1@94.6,48.2
NetDS3_2: DS3.2 R104.1 | length 2.6
  Bottom Layer w0.406: R104.1@93,44 93,44.15 93.503,44.653 94.453,44.653 DS3.2@95,45.2
NetJ1_12: J1.12 R56.2 U32.2 | length 7.5
  Top Layer w0.203: R56.2@44.95,46 45.28,45.67 47.97,45.67 48,45.7 48.03,45.67 J1.12@49.5,45.67
  Bottom Layer w0.203: U32.2@45.205,45.625 45.228,45.648 47.948,45.648 v1@48,45.7
  other v1: 48,45.67
NetJ1_13: J1.13 R55.2 U32.3 | length 7.8
  Top Layer w0.203: R55.2@44.95,44 44.95,44.1 45.498,44.648 45.598,44.648 45.82,44.87 47.97,44.87 48,44.9 48.03,44.87 J1.13@49.5,44.87
  Bottom Layer w0.203: U32.3@45.205,44.975 45.257,44.923 47.977,44.923 v1@48,44.9
  other v1: 48,44.87
NetJ1_18: J1.18 R53.1 U33.6 | length 8
  Top Layer w0.203: R53.1@44.95,41.5 44.95,41.4 45.498,40.852 47.948,40.852 v1@48,40.8 ; v1@48,40.848 49.478,40.848 J1.18@49.5,40.87
  Bottom Layer w0.203: U33.6@44.9,40.8 44.925,40.825 U33.6@45.195,40.825 v1(48,40.825)
NetJ1_19: J1.19 R54.2 U33.7 | length 7.7
  Top Layer w0.203: R54.2@44.95,39.5 44.95,39.522 45.498,40.07 47.871,40.07 v1@47.9,40.099 ; v1@47.9,40.1 47.93,40.07 v1(48,40.07) J1.19@49.5,40.07
  Bottom Layer w0.203: U33.7@45.2,40.1 45.223,40.123 47.948,40.123 v1(48,40.07)
NetJ4_1: J4.1 R102.2 R105.2 | length 8.6
  Top Layer w0.35: R102.2@86,29.9 86.1,29.9 86.725,29.275 86.725,29.175 87.4,28.5 J4.1@91.5,28.5
  Bottom Layer w0.35: R105.2@89.1,28.4 89.2,28.5 J4.1@91.5,28.5
NetP2_1: P2.1 R154.2 R157.2 R160.2 | length 20.3
  Bottom Layer w0.203: P2.1@-56.73,21.69 -51.286,21.69 -49.596,20 -44.15,20 -42.1,22.05 R160.2@-42,22.05 R157.2@-40,22.05 R154.2@-38,22.05
NetP2_3: P2.3 R164.2 R172.2 R177.2 | length 12.6
  Bottom Layer w0.203: P2.3@-56.73,24.23 -54.55,22.05 R177.2@-49,22.05 R172.2@-47,22.05 R164.2@-45,22.05
NetP2_5: P2.5 R165.2 R173.2 R178.2 | length 12.6
  Bottom Layer w0.203: P2.5@-56.73,26.77 -54.55,28.95 R178.2@-49,28.95 R173.2@-47,28.95 R165.2@-45,28.95
NetP2_7: P2.7 R155.2 R158.2 R161.2 | length 20.3
  Bottom Layer w0.203: P2.7@-56.73,29.31 -55.04,31 -44.15,31 -42.1,28.95 R161.2@-42,28.95 R158.2@-40,28.95 R155.2@-38,28.95
NetQ2_1: Q2.1 U21.7 | length 6
  Top Layer w0.127: Q2.1@27.55,-7 27.55,-7.05 28.397,-7.897 28.397,-9.997 29.1,-10.7 29.365,-10.7 29.8,-11.135 U21.7@30.6,-11.135
NetQ2_2: Q2.2 R139.2 U21.6 | length 53.5
  Top Layer w0.127: Q2.2@29.45,-7 29.45,-7.05 28.6,-7.9 28.6,-9.8 29.1,-10.3 29.365,-10.3 29.8,-9.865 U21.6@29.832,-9.865
  Top Layer w0.203: v2(29.2,-9.2) 29.2,-9.233 29.832,-9.865 U21.6@30.6,-9.865
  Bottom Layer w0.203: R139.2@-3,-31.55 ccw(c-3,-30.95) -2.4,-30.95 -2.4,-30.2 cw(c-0.391,-30.2) -0.391,-28.191 5.62,-28.191 ccw(c5.62,-26.223) 7.587,-26.223 7.587,-24.378 cw(c10.965,-24.378) 10.965,-21 20.348,-21 ccw(c20.348,-18.46) 22.144,-20.256 29.456,-12.944 ccw(c27.66,-11.148) 30.2,-11.148 ; v2(29.2,-9.2) 29.564,-9.564 cw(c28.027,-11.1) 30.2,-11.1
NetQ3_1: Q3.1 U21.1 | length 7.7
  Top Layer w0.127: Q3.1@32.05,-7 32.05,-7.05 32.875,-7.875 32.875,-11.475 33.5,-12.1 34.211,-12.1 34.516,-12.405 U21.1@35.4,-12.405
NetQ3_2: Q3.2 R46.1 U21.2 | length 9.8
  Top Layer w0.127: Q3.2@33.95,-7 33.95,-7.05 33.125,-7.875 33.125,-11.125 33.5,-11.5 34.235,-11.5 34.6,-11.135 U21.2@35.4,-11.135 37.685,-11.135 R46.1@38.05,-11.5
NetQ4_2: Q4.2 R93.1 U26.29 | length 10
  Top Layer w0.406: Q4.2@64.53,-31.358 64.67,-31.358 65.5,-31.358 R93.1@66.25,-31.358
  Int2 (Sign) w0.203: v4(57.25,-31.25) v4(65.5,-31.368)
NetQ4_4: Q4.4 R94.1 U26.31 | length 10.1
  Top Layer w0.406: Q4.4@64.53,-28.841 64.67,-28.841 65.5,-28.84 R94.1@66.25,-28.841
  Int2 (Sign) w0.203: v4(57.25,-30.25) v4(65.5,-28.85)
NetQ6_1: Q6.1 U35.5 | length 4.1
  Bottom Layer w0.406: Q6.1@24.05,-37.375 24.05,-37.35 25.828,-35.572 25.828,-34.522 25.9,-34.45 U35.5@26.35,-34.45
NetQ6_3: Q6.3 R37.1 U19.7 | length 4.7
  Top Layer w0.406: R37.1@25.65,-43 25.65,-40.285 25.732,-40.203 25.762,-40.203 26,-39.965 v2(26,-39.5)
  Bottom Layer w0.203: Q6.3@25,-39.625 25.793,-39.625 25.918,-39.5 v2(26,-39.5)
NetR2_1: R2.1 R8.2 U3.6 | length 13
  Top Layer w0.203: R2.1@-62.1,-38.6 -61.835,-38.865 U3.6@-54.9,-38.865 -54.1,-38.865 -53.45,-39.515 R8.2@-53.45,-43.5
NetR5_1: R5.1 U1.6 | length 3.1
  Top Layer w0.203: R5.1@-57.7,-7.6 -56.675,-8.625 U1.6@-56.675,-10.275
NetR6_1: R6.1 U5.6 | length 3.3
  Top Layer w0.203: R6.1@-53.9,-7.5 R6.1@-53.85,-7.5 -53.8,-7.5 -52.675,-8.625 U5.6@-52.675,-10.275
NetR7_1: R7.1 R11.2 U4.1 | length 10.5
  Top Layer w0.203: R7.1@-51.55,-26 -51.55,-31.255 -50.905,-31.9 U4.1@-50,-31.9 ; U4.1@-50.1,-31.905 -49.3,-31.905 -48.805,-32.4 -47.75,-32.4 -47.2,-32.95 R11.2@-47.1,-32.95
NetR8_1: R8.1 R9.2 U3.2 | length 10.1
  Top Layer w0.203: R9.2@-53.45,-35.5 -53.45,-37.585 U3.2@-50.9,-40.135 ; R8.1@-51.55,-43.5 -51.55,-40.785 U3.2@-50.9,-40.135 ; U3.2@-50.1,-40.135 U3.2@-50.9,-40.135
NetR10_1: R10.1 U6.6 | length 3.1
  Top Layer w0.203: U6.6@-48.6,-10.4 -48.598,-10.398 -48.598,-7.898 -48.2,-7.5 R10.1@-48.15,-7.5
NetR11_1: R11.1 R13.2 U4.2 | length 5
  Top Layer w0.127: R11.1@-46.5,-31.4 R11.1@-46.413,-31.487 ; R13.2@-45.563,-31.487 R13.2@-45.05,-32
  Top Layer w0.203: U4.2@-50.1,-30.635 -47.065,-30.635 R11.1@-46.8,-30.9 ; -46.313,-31.487 R13.2@-45.563,-31.487
NetR12_1: R12.1 U8.6 | length 2.7
  Top Layer w0.203: U8.6@-44.6,-10 -44.598,-9.998 -44.598,-7.898 -44.2,-7.5 R12.1@-44.15,-7.5
NetR14_1: R14.1 U12.4 | length 4.4
  Top Layer w0.203: R14.1@-43.15,-30 -42.602,-30.548 -42.602,-30.6 -40.9,-30.6 -40.525,-30.975 U12.4@-39.2,-30.975
NetR15_1: R15.1 U11.4 | length 5.7
  Top Layer w0.203: R15.1@-44.9,-40.4 -44.825,-40.475 U11.4@-39.2,-40.475
NetR16_2: R16.2 R18.1 R19.2 U9.2 U9.5 | length 11.7
  Top Layer w0.203: U9.2@-42.225,-3.775 -40.625,-3.775 -39.325,-5.075 U9.5@-37.775,-5.075 -36.075,-5.075 R19.2@-36,-5 ; R16.2@-41.5,-6.65 -40,-6.65 -38.55,-6.65 R18.1@-38.5,-6.6 ; R18.1@-38.5,-6.65 R18.1@-38.5,-6.6 ; U9.5@-37.7,-5.1 -37.7,-5.8 R18.1@-38.5,-6.6
NetR17_1: R17.1 U9.8 | length 2.2
  Top Layer w0.203: R17.1@-39,-1.7 -39,-1.8 -38.299,-2.501 -38.299,-3.002 -38.175,-3.125 U9.8@-37.775,-3.125
NetR17_2: R17.2 U9.1 | length 2.2
  Top Layer w0.203: U9.1@-42.225,-3.125 -41.824,-3.125 -41.701,-3.002 -41.701,-2.501 R17.2@-40.9,-1.7
NetR19_1: R19.1 R24.1 U9.6 | length 7.4
  Top Layer w0.203: U9.6@-37.775,-4.425 -37.652,-4.302 -37.102,-4.302 -36.498,-3.698 -36.398,-3.698 -36.1,-3.4 R19.1@-36.1,-3.3 ; R19.1@-36,-3.25 -31.05,-3.25 R24.1@-30.9,-3.4
NetR30_1: R30.1 R33.1 U18.9 U20.3 | length 14.1
  Top Layer w0.203: R30.1@17,27.623 17,27.723 20.952,31.675 R33.1@20.952,32.197 ; R33.1@21,32.5 20.952,32.452 R33.1@20.952,32.197 ; U20.3@27.365,32.34 27.365,32.487 26.352,33.5 25.105,33.5 24.05,32.445 U18.9@23.4,32.445 R33.1@21.3,32.445 21.2,32.445 R33.1@20.952,32.197
NetR31_1: R31.1 R44.1 U18.8 U20.2 | length 18.8
  Top Layer w0.203: R31.1@19,27.7 19,27.733 21.784,30.517 24.447,30.517 25.403,31.473 27.915,31.473 28.635,32.193 28.635,32.487 28.787,32.638 29.648,33.5 30.895,33.5 31.95,32.445 U18.8@32.6,32.445 R44.1@34.77,32.445
NetR32_1: R32.1 R35.1 U18.15 U20.5 | length 6.3
  Top Layer w0.203: R35.1@21.1,26.159 21.1,25.025 R32.1@21.3,24.825 U18.15@23.4,24.825 26.004,24.825 26.095,24.734 U20.5@26.095,24.66
NetR34_2: R34.2 R36.1 U16.L12 U18.16 U20.6 | length 51.2
  Top Layer w0.127: v1(-1,1) U16.L12@-0.5,0.5
  Top Layer w0.203: R34.2@21.3,23.555 U18.16@23.4,23.555 v1(26.75,23.555) ; R36.1@26.75,22 v1(26.75,23.555) ; U20.6@27.365,24.66 27.365,24.46 26.75,23.845 v1(26.75,23.555)
  Int2 (Sign) w0.127: v1(-1,1) cw(c-0.5,1) -0.5,1.5 6,1.5 ccw(c6,3) 7.5,3 7.5,10.448 cw(c10.04,10.448) 8.244,12.244 18.811,22.811 cw(c20.607,21.015) 20.607,23.555 v1(26.75,23.555)
NetR39_1: R39.1 R40.1 U18.1 U20.7 | length 8.1
  Top Layer w0.203: U20.7@28.635,24.66 28.635,23.555 ; R40.1@29.255,22 28.15,22 R39.1@28,22.15 28,22.92 28.635,23.555 ; U18.1@32.6,23.555 28.635,23.555
NetR43_1: R43.1 U18.3 | length 2.2
  Top Layer w0.35: U18.3@32.6,26.095 R43.1@34.77,26.095
NetR47_1: R47.1 U21.3 | length 2.8
  Top Layer w0.127: U21.3@35.4,-9.865 37.685,-9.865 R47.1@38.05,-9.5
NetR50_1: R50.1 U23.9 U25.2 | length 14.4
  Top Layer w0.203: U23.9@31.7,7.225 31.748,7.177 31.748,6.052 32.3,5.5 35,5.5 37,7.5 40,7.5 ; U25.2@40,8.65 40,7.5 ; R50.1@42.55,7 40.5,7 40,7.5
NetR51_1: R51.1 U23.5 U25.1 | length 20
  Top Layer w0.203: U23.5@32.35,12.775 32.35,14.3 cw(c33.05,14.3) 33.05,15 40.942,15 R51.1@42.142,15 ; U25.1@39.05,8.65 39.05,9.1 39.95,10 41.5,10 42.002,10.502 R51.1@42.002,14.802
NetR52_1: R52.1 R58.1 U26.6 | length 9.2
  Top Layer w0.203: R52.1@42.85,-32.079 v4(42.85,-31.187) R58.1@42.85,-30.212 ; v4(49.5,-30.25) U26.6@50.075,-30.25
  Int2 (Sign) w0.203: v4(42.85,-31.187) v4(49.5,-30.25)
NetR61_1: R61.1 R73.2 U26.17 | length 12.2
  Top Layer w0.203: R61.1@50.45,-43 51.236,-43 51.986,-42.25 v4(52,-42.25) 52,-42.236 52.752,-41.485 52.752,-41.148 R73.2@53,-40.9 ; v4(52.75,-34.5) U26.17@52.75,-33.925
  Bottom Layer w0.203: v4(52,-42.25) ccw(c50.793,-41.043) 52.5,-41.043 52.5,-35.103 cw(c53.353,-35.103) v4(52.75,-34.5)
NetR62_2: R62.2 R63.2 R71.1 U26.13 | length 9.9
  Top Layer w0.203: R62.2@50.312,-41.694 50.402,-41.783 cw(c50.285,-41.9) R62.2@50.45,-41.9 50.45,-40.85 R63.2@50.4,-40.8 ; R63.2@50.5,-40.8 50.55,-40.75 v4(51.3,-40.75) 51.95,-40.75 R71.1@52.1,-40.9 ; v4@50.749,-34.499 U26.13@50.75,-33.925
  Int2 (Sign) w0.203: v4(50.748,-34.5) v4(51.3,-40.75)
NetR65_2: R65.2 U26.15 | length 2.4
  Top Layer w0.203: R65.2@50.398,-35.225 51.252,-35.225 51.75,-34.726 U26.15@51.75,-33.925
NetR66_2: R66.2 U26.46 | length 1.6
  Top Layer w0.203: R66.2@51.3,-25.65 51.548,-25.898 51.548,-26.237 51.741,-26.429 51.741,-27.066 U26.46@51.75,-27.075
NetR67_1: R67.1 R69.1 U26.16 | length 4.6
  Top Layer w0.203: U26.16@52.25,-33.925 52.25,-35.25 51.9,-35.6 51.9,-36.133 51.898,-36.134 51.898,-36.252 51.65,-36.5 51.898,-36.748 51.898,-36.798 52.502,-37.402 52.502,-37.552 52.575,-37.625 R67.1@52.8,-37.625
NetR68_1: R68.1 R70.1 U26.45 | length 6.1
  Top Layer w0.203: R70.1@51.6,-23 R70.1@51.662,-23.062 ; U26.45@52.25,-27.075 52.241,-27.066 52.241,-26.462 51.9,-26.121 51.9,-23.248 51.714,-23.062 R70.1@51.662,-23.062 ; R68.1@52.9,-22 52.8,-22 52.552,-22.248 52.477,-22.248 R70.1@51.662,-23.062
NetR74_1: R74.1 R83.2 R84.2 U26.18 | length 13.4
  Top Layer w0.203: v4@53.251,-34.499 U26.18@53.25,-33.925 ; R74.1@54.2,-41.1 54.248,-41.148 54.248,-41.498 v4(55,-42.25) 55.75,-43 R83.2@56.65,-43 56.7,-42.95 R84.2@56.7,-41.9
  Bottom Layer w0.203: v4(53.252,-34.5) 53.252,-35.15 ccw(c54.1,-35.15) 53.5,-35.75 53.756,-36.006 cw(c51.96,-37.802) 54.5,-37.802 54.5,-41.043 ccw(c56.207,-41.043) v4(55,-42.25)
NetR75_1: R75.1 R77.1 U26.21 | length 5.2
  Top Layer w0.203: R77.1@54.15,-37.8 54.25,-37.8 54.498,-37.552 54.498,-37.402 55.102,-36.798 55.102,-36.748 55.35,-36.5 R75.1@55.45,-36.5 ; U26.21@54.75,-33.925 54.75,-35.25 55.114,-35.614 55.114,-36.314 55.3,-36.5 R75.1@55.4,-36.5 ; R75.1@55.239,-36.251 R75.1@55.425,-36.437 ; R75.1@55.362,-36.437 R75.1@55.425,-36.5
NetR76_1: R76.1 R78.1 U26.40 | length 6.2
  Top Layer w0.203: R78.1@54.1,-22 54.2,-22 54.448,-22.248 54.525,-22.248 R76.1@55.288,-23.011 ; U26.40@54.75,-27.075 54.75,-26.398 55.052,-26.096 v4(55.052,-23.625) 55.052,-23.248 R76.1@55.288,-23.011 ; R76.1@55.338,-23.061 R76.1@55.288,-23.011 ; R76.1@55.338,-23.012 55.35,-23 R76.1@55.45,-23 ; R76.1@55.388,-23.062 R76.1@55.452,-23.125
NetR80_1: R80.1 U26.41 | length 1.3
  Top Layer w0.203: U26.41@54.25,-27.075 54.25,-25.895 R80.1@54.37,-25.775
NetR81_1: R81.1 R85.2 R116.2 U26.19 | length 10
  Top Layer w0.203: v4(53.75,-34.5) U26.19@53.75,-33.925 ; R81.1@55,-41 55.25,-40.75 v4(55.8,-40.75) 56.55,-40.75 R85.2@56.6,-40.8
  Bottom Layer w0.203: v4(53.75,-34.5) 53.75,-34.746 ccw(c54.604,-34.746) 54,-35.35 55.056,-36.406 cw(c53.26,-38.202) 55.8,-38.202 v4(55.8,-40.75) R116.2@56.5,-40.75
NetR82_2: R82.2 U26.39 | length 1.7
  Top Layer w0.203: U26.39@55.25,-27.075 55.259,-27.066 55.259,-26.442 55.452,-26.249 55.452,-25.859 R82.2@55.759,-25.551
NetR86_2: R86.2 U26.22 | length 2.4
  Top Layer w0.203: U26.22@55.25,-33.925 U26.22@55.25,-33.925 55.25,-34.725 55.75,-35.225 R86.2@56.625,-35.225
NetR87_1: R87.1 R95.2 | length 20.6
  Top Layer w0.203: R87.1@62.9,12.1 R87.1@62.95,12.1 ; R87.1@62.95,12 64.46,12 cw(c64.46,9.46) 67,9.46 R95.2@67,-5.55
NetR88_2: R88.2 R89.1 U28.6 | length 6.5
  Top Layer w0.203: U28.6@57.9,10.365 57.976,10.289 59.061,10.289 60.502,8.849 60.85,8.5 R89.1@60.9,8.5 ; R89.1@61.05,8.2 R88.2@62.95,6.2
NetR100_1: R100.1 T1.3 U29.3 | length 5.7
  Top Layer w0.35: U29.3@73.205,28.825 74.425,28.825 74.775,29.175 74.775,29.275 75.6,30.1 R100.1@75.7,30.1 ; R100.1@75.5,30 75.55,29.95 75.73,29.77 T1.3@78,29.77
NetR100_2: R100.2 T1.1 U29.2 | length 5.2
  Top Layer w0.35: U29.2@73.205,28.175 74.425,28.175 74.775,27.825 74.775,27.725 75.3,27.2 R100.2@75.4,27.2 ; R100.2@75.5,27.2 75.53,27.23 T1.1@78,27.23
NetR101_2: R101.2 R102.1 T1.6 TP26.1 | length 8.6
  Top Layer w0.35: TP26.1@79.5,24.5 81.2,26.2 T1.6@81.2,27.2 ; T1.6@81.175,27.23 86.37,27.23 R102.1@86.4,27.2
NetR109_1: R109.1 R114.2 U26.5 U26.37 | length 14.6
  Top Layer w0.203: v4(49.5,-29.75) U26.5@50.075,-29.75 ; U26.37@56.25,-27.075 56.259,-27.066 56.25,-27.057 56.25,-26.578 v4(56.4,-26.428)
  Int2 (Sign) w0.203: v4(49.5,-29.75) 49.5,-27.5 cw(c51,-27.5) 51,-26 55.972,-26 cw(c55.972,-26.428) v4(56.4,-26.428)
  Bottom Layer w0.203: v4(56.4,-26.428) 57.347,-26.428 57.9,-25.875 R114.2@57.9,-25.65
  Bottom Layer w0.508: R114.2@57.9,-25.65 R109.1@59,-25.65
NetR115_2: R115.2 R117.1 U26.38 | length 2.5
  Top Layer w0.203: U26.38@55.75,-27.075 55.759,-27.066 55.749,-27.056 55.749,-26.503 v4(55.824,-26.428)
  Bottom Layer w0.203: v4(55.824,-26.428) R117.1@55.824,-25.713
  Bottom Layer w0.508: R117.1@55.7,-25.65 R115.2@56.8,-25.65
NetR118_1: R118.1 R119.1 R120.1 U26.43 | length 4.7
  Top Layer w0.203: U26.43@53.25,-27.075 v4@53.25,-26.5
  Bottom Layer w0.203: R120.1@52.5,-24.35 R119.1@53.5,-25.65 ; v4(53.25,-26.437) 53.252,-26.436 53.252,-25.898 R119.1@53.5,-25.65 ; R118.1@54.4,-24.35 R119.1@53.5,-25.65
NetR121_1: R121.1 R124.2 U26.47 | length 2
  Top Layer w0.203: U26.47@51.248,-26.774 v4@51.248,-26.491 ; U26.47@51.25,-27.075 U26.47@51.275,-27.05
  Bottom Layer w0.203: v4(51.173,-26.428) R121.1@51.173,-25.777
  Bottom Layer w0.508: R124.2@50.3,-25.65 R121.1@51.3,-25.65
NetR122_2: R122.2 R123.1 U26.14 | length 2.4
  Top Layer w0.203: v4(51.248,-34.5) U26.14@51.249,-33.926
  Bottom Layer w0.203: R123.1@50.7,-33.75 51.106,-34.156 cw(c50.762,-34.5) v4(51.248,-34.5) cw(c50.519,-34.5) 51.035,-35.015 R122.2@50.8,-35.25
NetR125_1: R125.1 R126.2 U26.48 | length 4.3
  Top Layer w0.203: U26.48@50.748,-27.073 U26.48@50.75,-27.075 50.755,-27.07 50.748,-27.064 v4(50.748,-26.437)
  Bottom Layer w0.203: R126.2@48,-24.4 R125.1@49.3,-25.65 ccw(c49.785,-25.65) 49.442,-25.993 49.549,-26.1 ccw(c50.364,-25.285) 50.364,-26.437 v4(50.748,-26.437)
NetR127_1: R127.1 R128.1 U34.2 | length 3.8
  Bottom Layer w0.203: R128.1@35.2,4.35 R127.1@35.2,2.75 35.315,2.865 U34.2@37.4,2.865
NetR135_1: R135.1 U36.5 U37.4 | length 29.1
  Int3 (Sign) w0.127: v1(-19.825,-7.975) -15.256,-12.544 ccw(c-12.948,-10.236) -13.625,-13.429 ccw(c-12.948,-10.236) -12.948,-13.5 -5.052,-13.5 cw(c-5.052,-16.04) -3.256,-14.244 v1(1,-18.5)
  Bottom Layer w0.203: v1(-19.825,-7.975) U37.4@-19.825,-6.684 ; U36.5@-0.8,-18.5 v1(1,-18.5) R135.1@2.1,-18.5
NetR136_2: R136.2 U21.5 | length 49
  Top Layer w0.203: U21.5@30.6,-8.7 cw(c30.841,-8.941) U21.5@30.841,-8.6 ; U21.5@30.6,-8.595 31.397,-8.595 32,-9.198 v2(32,-9.2)
  Bottom Layer w0.203: R136.2@-1,-31.55 cw(c-1,-30.943) -1.607,-30.943 -1.607,-30.244 cw(c-0.391,-30.244) -0.391,-29.028 5.62,-29.028 ccw(c5.62,-26.223) 8.425,-26.223 8.425,-24.378 cw(c10.965,-24.378) 10.965,-21.838 20.348,-21.838 ccw(c20.348,-18.46) 22.736,-20.848 30.048,-13.536 ccw(c27.66,-11.148) 31.038,-11.148 cw(c33.417,-11.148) 31.735,-9.465 v2(32,-9.2)
NetR137_2: R137.2 U36.6 | length 0.9
  Bottom Layer w0.203: U36.6@-0.9,-19.1 -0.85,-19.15 R137.2@-0.85,-20
NetR138_2: R138.2 R140.1 U36.7 | length 3
  Bottom Layer w0.203: U36.7@-5.2,-19.1 U36.7@-5.15,-19.15 ; U36.7@-5.184,-19.125 -5.07,-19.239 -4.461,-19.239 -4.187,-19.513 -4.187,-19.752 -4.039,-19.9 R140.1@-3.8,-19.9 ; R140.1@-3.85,-20 -3.85,-20.752 -3.702,-20.9 R138.2@-3.6,-20.9
NetR144_1: R144.1 U16.F8 | length 10.2
  Top Layer w0.127: v1(-6,-4) U16.F8@-5.5,-3.5
  Bottom Layer w0.127: R144.1@-14.8,-2.5 R144.1@-14.75,-2.5 ; R144.1@-14.6,-2.5 -13.344,-3.756 ccw(c-11.548,-1.96) -11.548,-4.5 -7.207,-4.5 ccw(c-7.207,-2.793) v1(-6,-4)
NetR145_2: R145.2 R146.2 R147.1 U38.4 | length 8
  Bottom Layer w0.203: R146.2@-17.2,-36.65 -18.35,-36.65 U38.4@-18.35,-36.95 R147.1@-18.35,-38.5 -17.744,-39.106 cw(c-19.54,-40.902) -17,-40.902 R145.2@-17,-43.05
NetR150_2: R150.2 U37.6 | length 0.9
  Bottom Layer w0.203: R150.2@-22,-6.6 -21.916,-6.684 U37.6@-21.125,-6.684
NetR151_2: R151.2 R152.1 U37.7 | length 2.1
  Bottom Layer w0.203: R152.1@-23,-2.05 R151.2@-22,-2.05 -21.239,-2.05 -21.125,-2.164 U37.7@-21.125,-2.316
NetR154_1: R154.1 U10.6 | length 3.6
  Top Layer w0.203: U10.6@-38.7,22.725 -38.7,24.3 v1(-38,25)
  Bottom Layer w0.203: R154.1@-38,23.95 v1(-38,25)
NetR155_1: R155.1 U10.8 | length 3.3
  Top Layer w0.203: U10.8@-38.05,28.275 -38.025,28.25 -38.025,26.025 v1(-38,26)
  Bottom Layer w0.203: v1(-38,26) R155.1@-38,27.05
NetR157_1: R157.1 U10.4 | length 3.3
  Top Layer w0.203: U10.4@-40,22.725 v1(-40,25)
  Bottom Layer w0.203: R157.1@-40,23.95 v1(-40,25)
NetR158_1: R158.1 U10.10 | length 3.6
  Top Layer w0.203: v1(-40,26) -39.35,26.65 U10.10@-39.35,28.275
  Bottom Layer w0.203: v1(-40,26) R158.1@-40,27.05
NetR160_1: R160.1 U10.2 | length 3.6
  Top Layer w0.203: v1(-42,25) -41.3,24.3 U10.2@-41.3,22.725
  Bottom Layer w0.203: R160.1@-42,23.95 v1(-42,25)
NetR161_1: R161.1 U10.12 | length 4.2
  Top Layer w0.203: v1(-42,26) -41.5,26 -40.65,26.85 U10.12@-40.65,28.275
  Bottom Layer w0.203: v1(-42,26) R161.1@-42,27.05
NetR163_1: R163.1 R167.2 U8.5 | length 4.8
  Top Layer w0.203: U8.5@-44.025,-10.275 -44.02,-10.28 v3(-44.02,-11.5)
  Bottom Layer w0.203: R167.2@-45,-14.35 -43.6,-12.65 -43.998,-12.252 -43.998,-11.521 v3(-44.02,-11.5)
NetR164_1: R164.1 U7.6 | length 3.6
  Top Layer w0.203: U7.6@-45.7,22.725 -45.7,24.3 v1(-45,25)
  Bottom Layer w0.203: R164.1@-45,23.95 v1(-45,25)
NetR165_1: R165.1 U7.8 | length 3.3
  Top Layer w0.203: U7.8@-45.05,28.275 -45.025,28.25 -45.025,26.025 v1(-45,26)
  Bottom Layer w0.203: v1(-45,26) R165.1@-45,27.05
NetR169_1: R169.1 U8.8 | length 2.5
  Top Layer w0.203: v3(-45.975,-11.5) U8.8@-45.975,-10.275
  Bottom Layer w0.203: R169.1@-46.3,-12.65 -45.975,-12.325 v3(-45.975,-11.5)
NetR169_2: R169.2 U8.1 | length 2.5
  Top Layer w0.203: v3(-45.975,-15.7) U8.1@-45.975,-14.725
  Bottom Layer w0.203: R169.2@-46.3,-14.35 -45.975,-14.675 v3(-45.975,-15.7)
NetR172_1: R172.1 U7.4 | length 3.3
  Top Layer w0.203: U7.4@-47,22.725 v1(-47,25)
  Bottom Layer w0.203: R172.1@-47,23.95 v1(-47,25)
NetR173_1: R173.1 U7.10 | length 3.6
  Top Layer w0.203: v1(-47,26) -46.35,26.65 U7.10@-46.35,28.275
  Bottom Layer w0.203: v1(-47,26) R173.1@-47,27.05
NetR174_1: R174.1 R179.2 U6.5 | length 4.8
  Top Layer w0.203: v3(-48.025,-11.5) U6.5@-48.025,-10.275
  Bottom Layer w0.203: R179.2@-49,-14.35 -47.6,-12.65 -47.998,-12.252 -47.998,-11.527 v3(-48.025,-11.5)
NetR177_1: R177.1 U7.2 | length 3.6
  Top Layer w0.203: v1(-49,25) -48.3,24.3 U7.2@-48.3,22.725
  Bottom Layer w0.203: R177.1@-49,23.95 v1(-49,25)
NetR178_1: R178.1 U7.12 | length 4.2
  Top Layer w0.203: v1(-49,26) -48.5,26 -47.65,26.85 U7.12@-47.65,28.275
  Bottom Layer w0.203: v1(-49,26) R178.1@-49,27.05
NetR185_1: R185.1 U6.8 | length 2.5
  Top Layer w0.203: v3(-49.975,-11.5) U6.8@-49.975,-10.275
  Bottom Layer w0.203: R185.1@-50.3,-12.65 -49.975,-12.325 v3(-49.975,-11.5)
NetR185_2: R185.2 U6.1 | length 2.5
  Top Layer w0.203: v3(-49.975,-15.7) U6.1@-49.975,-14.725
  Bottom Layer w0.203: R185.2@-50.3,-14.35 -49.975,-14.675 v3(-49.975,-15.7)
NetR188_1: R188.1 R191.2 U5.5 | length 4.7
  Top Layer w0.203: v3(-52.025,-11.5) U5.5@-52.025,-10.275
  Bottom Layer w0.203: R191.2@-53,-14.35 -52.951,-14.29 R188.1@-51.6,-12.65 ; v3(-52.025,-11.5) -51.998,-11.527 -51.998,-12.152 R188.1@-51.6,-12.55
